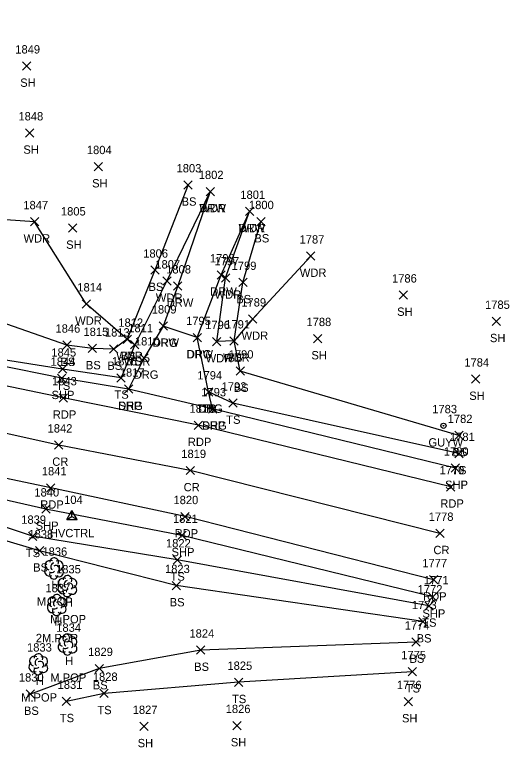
# Model space of a CAD drawing. Extents: x 1497084 to 1499861, y 734741 to 735567.
# Drawn here: x 1499741.8 to 1499860.6, y 735362.7 to 735538.6 of the extents above; entities that cross this region are included whole.
import ezdxf

# ---------------------------------------------------------------- set-up
doc = ezdxf.new("R2010")
doc.units = 0
for name, color, linetype in [('C_A', 7, 'Continuous'), ('C_I', 7, 'Continuous'), ('CPSM', 7, 'Continuous'), ('L_A', 7, 'Continuous'), ('L_C', 7, 'Continuous'), ('L_I', 7, 'Continuous'), ('L_TIC', 7, 'Continuous'), ('LAWA', 7, 'Continuous'), ('LELB', 7, 'Continuous'), ('LTD', 7, 'Continuous'), ('P_A', 7, 'Continuous'), ('P_I', 7, 'Continuous'), ('P_TIC', 7, 'Continuous'), ('PET', 7, 'Continuous'), ('PRC', 7, 'Continuous'), ('PSP', 7, 'Continuous'), ('R_A', 7, 'Continuous'), ('R_I', 7, 'Continuous'), ('R_TIC', 7, 'Continuous'), ('RDG', 7, 'Continuous'), ('RDW', 7, 'Continuous'), ('U_A', 7, 'Continuous'), ('U_I', 7, 'Continuous'), ('UPGW', 7, 'Continuous')]:
    doc.layers.add(name, color=color, linetype=linetype)

msp = doc.modelspace()

# ---------------------------------------------------------------- linework, layer by layer
at = {"layer": 'CPSM'}
for p, q in [((1499754.27, 735417.41), (1499755.52, 735419.57)), ((1499754.27, 735417.41), (1499755.52, 735418.13)), ((1499756.77, 735417.41), (1499755.52, 735419.57)), ((1499755.52, 735418.13), (1499755.52, 735419.57)), ((1499755.52, 735418.13), (1499755.52, 735418.13)), ((1499755.52, 735418.13), (1499756.77, 735417.41)), ((1499754.27, 735417.41), (1499756.77, 735417.41))]:
    msp.add_line(p, q, dxfattribs=at)
at = {"layer": 'L_TIC'}
for points in [[(1499743.61, 735525.3), (1499745.61, 735527.3)], [(1499745.61, 735525.3), (1499743.61, 735527.3)], [(1499744.36, 735509.23), (1499746.36, 735511.23)], [(1499746.36, 735509.23), (1499744.36, 735511.23)], [(1499760.88, 735501.14), (1499762.88, 735503.14)], [(1499762.88, 735501.14), (1499760.88, 735503.14)], [(1499782.41, 735496.75), (1499784.41, 735498.75)], [(1499784.41, 735496.75), (1499782.41, 735498.75)], [(1499787.74, 735495.15), (1499789.74, 735497.15)], [(1499789.74, 735495.15), (1499787.74, 735497.15)], [(1499797.16, 735490.39), (1499799.16, 735492.39)], [(1499799.16, 735490.39), (1499797.16, 735492.39)], [(1499745.53, 735487.9), (1499747.53, 735489.9)], [(1499747.53, 735487.9), (1499745.53, 735489.9)], [(1499799.89, 735487.93), (1499801.89, 735489.93)], [(1499801.89, 735487.93), (1499799.89, 735489.93)], [(1499754.65, 735486.4), (1499756.65, 735488.4)], [(1499756.65, 735486.4), (1499754.65, 735488.4)], [(1499811.88, 735479.66), (1499813.88, 735481.66)], [(1499813.88, 735479.66), (1499811.88, 735481.66)], [(1499774.46, 735476.28), (1499776.46, 735478.28)], [(1499776.46, 735476.28), (1499774.46, 735478.28)], [(1499791.43, 735474.42), (1499793.43, 735476.42)], [(1499793.43, 735474.42), (1499791.43, 735476.42)], [(1499777.31, 735473.67), (1499779.31, 735475.67)], [(1499779.31, 735473.67), (1499777.31, 735475.67)], [(1499795.56, 735473.32), (1499797.56, 735475.32)], [(1499797.56, 735473.32), (1499795.56, 735475.32)], [(1499834.12, 735470.3), (1499836.12, 735472.3)], [(1499836.12, 735470.3), (1499834.12, 735472.3)], [(1499757.94, 735468.15), (1499759.94, 735470.15)], [(1499759.94, 735468.15), (1499757.94, 735470.15)], [(1499797.89, 735464.54), (1499799.89, 735466.54)], [(1499799.89, 735464.54), (1499797.89, 735466.54)], [(1499856.41, 735463.98), (1499858.41, 735465.98)], [(1499858.41, 735463.98), (1499856.41, 735465.98)], [(1499753.32, 735458.26), (1499755.32, 735460.26)], [(1499755.32, 735458.26), (1499753.32, 735460.26)], [(1499767.79, 735459.68), (1499769.79, 735461.68)], [(1499769.79, 735459.68), (1499767.79, 735461.68)], [(1499767.79, 735459.68), (1499769.79, 735461.68)], [(1499769.79, 735459.68), (1499767.79, 735461.68)], [(1499769.6, 735458.37), (1499771.6, 735460.37)], [(1499771.6, 735458.37), (1499769.6, 735460.37)], [(1499769.6, 735458.37), (1499771.6, 735460.37)], [(1499771.6, 735458.37), (1499769.6, 735460.37)], [(1499789.27, 735459.12), (1499791.27, 735461.12)], [(1499791.27, 735459.12), (1499789.27, 735461.12)], [(1499793.46, 735459.27), (1499795.46, 735461.27)], [(1499795.46, 735459.27), (1499793.46, 735461.27)], [(1499793.46, 735459.27), (1499795.46, 735461.27)], [(1499795.46, 735459.27), (1499793.46, 735461.27)], [(1499813.53, 735459.84), (1499815.53, 735461.84)], [(1499815.53, 735459.84), (1499813.53, 735461.84)], [(1499759.42, 735457.46), (1499761.42, 735459.46)], [(1499761.42, 735457.46), (1499759.42, 735459.46)], [(1499764.57, 735457.33), (1499766.57, 735459.33)], [(1499766.57, 735457.33), (1499764.57, 735459.33)], [(1499752.27, 735452.51), (1499754.27, 735454.51)], [(1499754.27, 735452.51), (1499752.27, 735454.51)], [(1499794.94, 735452.04), (1499796.94, 735454.04)], [(1499796.94, 735452.04), (1499794.94, 735454.04)], [(1499766.32, 735450.4), (1499768.32, 735452.4)], [(1499768.32, 735450.4), (1499766.32, 735452.4)], [(1499851.45, 735450.11), (1499853.45, 735452.11)], [(1499853.45, 735450.11), (1499851.45, 735452.11)], [(1499787.32, 735447.02), (1499789.32, 735449.02)], [(1499789.32, 735447.02), (1499787.32, 735449.02)], [(1499793.16, 735444.36), (1499795.16, 735446.36)], [(1499795.16, 735444.36), (1499793.16, 735446.36)], [(1499847.45, 735436.58), (1499849.45, 735438.58)], [(1499849.45, 735436.58), (1499847.45, 735438.58)], [(1499847.43, 735432.23), (1499849.43, 735434.23)], [(1499849.43, 735432.23), (1499847.43, 735434.23)], [(1499745.05, 735412.36), (1499747.05, 735414.36)], [(1499747.05, 735412.36), (1499745.05, 735414.36)], [(1499746.75, 735408.88), (1499748.75, 735410.88)], [(1499748.75, 735408.88), (1499746.75, 735410.88)], [(1499779.79, 735406.69), (1499781.79, 735408.69)], [(1499781.79, 735406.69), (1499779.79, 735408.69)], [(1499779.55, 735400.53), (1499781.55, 735402.53)], [(1499781.55, 735400.53), (1499779.55, 735402.53)], [(1499840.23, 735395.64), (1499842.23, 735397.64)], [(1499842.23, 735395.64), (1499840.23, 735397.64)], [(1499838.85, 735391.86), (1499840.85, 735393.86)], [(1499840.85, 735391.86), (1499838.85, 735393.86)], [(1499837.14, 735386.97), (1499839.14, 735388.97)], [(1499839.14, 735386.97), (1499837.14, 735388.97)], [(1499785.43, 735385.03), (1499787.43, 735387.03)], [(1499787.43, 735385.03), (1499785.43, 735387.03)], [(1499761.09, 735380.61), (1499763.09, 735382.61)], [(1499763.09, 735380.61), (1499761.09, 735382.61)], [(1499836.28, 735379.85), (1499838.28, 735381.85)], [(1499838.28, 735379.85), (1499836.28, 735381.85)], [(1499794.55, 735377.29), (1499796.55, 735379.29)], [(1499796.55, 735377.29), (1499794.55, 735379.29)], [(1499744.54, 735374.47), (1499746.54, 735376.47)], [(1499746.54, 735374.47), (1499744.54, 735376.47)], [(1499762.22, 735374.64), (1499764.22, 735376.64)], [(1499764.22, 735374.64), (1499762.22, 735376.64)], [(1499753.2, 735372.72), (1499755.2, 735374.72)], [(1499755.2, 735372.72), (1499753.2, 735374.72)], [(1499835.28, 735372.67), (1499837.28, 735374.67)], [(1499837.28, 735372.67), (1499835.28, 735374.67)], [(1499794.18, 735366.91), (1499796.18, 735368.91)], [(1499796.18, 735366.91), (1499794.18, 735368.91)], [(1499771.8, 735366.7), (1499773.8, 735368.7)], [(1499773.8, 735366.7), (1499771.8, 735368.7)]]:
    msp.add_lwpolyline(points, dxfattribs=at)
at = {"layer": 'LAWA'}
for points in [[(1499788.74, 735496.15), (1499778.31, 735474.67), (1499770.6, 735459.37), (1499768.79, 735460.68), (1499758.94, 735469.15), (1499746.53, 735488.9), (1499729.21, 735490.09), (1499697.8, 735511.88), (1499637.79, 735524.78), (1499612.73, 735535.09), (1499594.49, 735538.63)], [(1499812.88, 735480.66), (1499798.89, 735465.54), (1499794.46, 735460.27), (1499790.27, 735460.12), (1499792.43, 735475.42), (1499798.16, 735491.39)]]:
    msp.add_lwpolyline(points, dxfattribs=at)
at = {"layer": 'LELB'}
for points in [[(1499783.41, 735497.75), (1499775.46, 735477.28), (1499768.79, 735460.68), (1499765.57, 735458.33), (1499760.42, 735458.46), (1499754.32, 735459.26), (1499738.22, 735464.85), (1499726.1, 735470.25), (1499689.55, 735474.19)], [(1499848.45, 735437.58), (1499795.94, 735453.04), (1499794.46, 735460.27), (1499796.56, 735474.32), (1499800.89, 735488.93)], [(1499770.6, 735459.37), (1499767.32, 735451.4), (1499753.27, 735453.51), (1499723.33, 735458.19), (1499688.04, 735465.79), (1499662, 735476.73), (1499649.94, 735471.98), (1499600.23, 735477.81), (1499596.97, 735472.37)], [(1499848.43, 735433.23), (1499794.16, 735445.36), (1499788.32, 735448.02)], [(1499839.85, 735392.86), (1499780.55, 735401.53), (1499747.75, 735409.88), (1499711.76, 735420.6), (1499681.47, 735424.66), (1499665.96, 735425.75), (1499648.83, 735427.4), (1499598.57, 735431.68), (1499589.95, 735436.64), (1499584.82, 735440.49), (1499583.81, 735444.46), (1499585.42, 735446.56), (1499592.69, 735446.66)], [(1499841.23, 735396.64), (1499780.79, 735407.69), (1499746.05, 735413.36), (1499713.07, 735424.39), (1499683.25, 735430.83), (1499665.3, 735431.61), (1499657.01, 735431.78), (1499644.89, 735434.35), (1499602.81, 735439.91), (1499596.15, 735442.52), (1499594.16, 735445.59)], [(1499838.14, 735387.97), (1499786.43, 735386.03), (1499762.09, 735381.61), (1499745.54, 735375.47)], [(1499837.28, 735380.85), (1499795.55, 735378.29), (1499763.22, 735375.64), (1499754.2, 735373.72)]]:
    msp.add_lwpolyline(points, dxfattribs=at)
at = {"layer": 'LTD'}
for p, q in [((1499751.18, 735405.69), (1499751.18, 735405.69)), ((1499751.18, 735405.69), (1499751.18, 735405.69)), ((1499754.39, 735401.46), (1499754.39, 735401.46)), ((1499754.39, 735401.46), (1499754.39, 735401.46)), ((1499751.84, 735396.93), (1499751.84, 735396.93)), ((1499751.84, 735396.93), (1499751.84, 735396.93)), ((1499754.43, 735387.42), (1499754.43, 735387.42)), ((1499754.43, 735387.42), (1499754.43, 735387.42)), ((1499747.42, 735382.68), (1499747.42, 735382.68)), ((1499747.42, 735382.68), (1499747.42, 735382.68))]:
    msp.add_line(p, q, dxfattribs=at)
for centre in [(1499751.23, 735407.13), (1499754.44, 735402.89), (1499751.88, 735398.36), (1499754.48, 735388.85), (1499747.47, 735384.12)]:
    msp.add_arc(centre, 1.05, 335.5272, 180.9563, dxfattribs=at)
for centre, major_axis, ratio, start_param, end_param in [((1499750.39, 735406.36), (1.21, -0.51), 0.895232, 1.570796, 4.712389), ((1499752.22, 735406.28), (-1.14, -0.48), 0.949671, 1.570796, 4.712389), ((1499750.1, 735404.98), (0.58, -1.04), 0.959034, 3.141593, 6.283185), ((1499750.97, 735406.15), (-0.208, -0.792), 0.645439, 3.141593, 6.283185), ((1499751.68, 735405.53), (-0.5, 0.667), 0.989748, 3.141593, 6.283185), ((1499752.18, 735404.86), (-1.09, 0.79), 0.841452, 1.570796, 4.712389), ((1499751.18, 735404.19), (0.26, 1.06), 0.942809, 1.570796, 4.712389), ((1499750.72, 735404.94), (-0.625, -0.083), 0.423636, 0, 3.141593), ((1499753.6, 735402.12), (1.21, -0.51), 0.895232, 1.570796, 4.712389), ((1499754.19, 735401.92), (-0.208, -0.792), 0.645439, 3.141593, 6.283185), ((1499754.89, 735401.29), (-0.5, 0.667), 0.989748, 3.141593, 6.283185), ((1499755.44, 735402.04), (-1.14, -0.48), 0.949671, 1.570796, 4.712389), ((1499753.31, 735400.75), (0.58, -1.04), 0.959034, 3.141593, 6.283185), ((1499753.94, 735400.71), (-0.625, -0.083), 0.423636, 0, 3.141593), ((1499755.39, 735400.63), (-1.09, 0.79), 0.841452, 1.570796, 4.712389), ((1499751.05, 735397.59), (1.21, -0.51), 0.895232, 1.570796, 4.712389), ((1499752.88, 735397.51), (-1.14, -0.48), 0.949671, 1.570796, 4.712389), ((1499754.4, 735399.96), (0.26, 1.06), 0.942809, 1.570796, 4.712389), ((1499750.75, 735396.22), (0.58, -1.04), 0.959034, 3.141593, 6.283185), ((1499751.63, 735397.39), (-0.208, -0.792), 0.645439, 3.141593, 6.283185), ((1499752.34, 735396.76), (-0.5, 0.667), 0.989748, 3.141593, 6.283185), ((1499752.84, 735396.09), (-1.09, 0.79), 0.841452, 1.570796, 4.712389), ((1499751.84, 735395.43), (0.26, 1.06), 0.942809, 1.570796, 4.712389), ((1499751.38, 735396.18), (-0.625, -0.083), 0.423636, 0, 3.141593), ((1499753.64, 735388.08), (1.21, -0.51), 0.895232, 1.570796, 4.712389), ((1499754.23, 735387.87), (-0.208, -0.792), 0.645439, 3.141593, 6.283185), ((1499754.93, 735387.25), (-0.5, 0.667), 0.989748, 3.141593, 6.283185), ((1499755.48, 735388), (-1.14, -0.48), 0.949671, 1.570796, 4.712389), ((1499753.35, 735386.71), (0.58, -1.04), 0.959034, 3.141593, 6.283185), ((1499753.98, 735386.67), (-0.625, -0.083), 0.423636, 0, 3.141593), ((1499755.44, 735386.58), (-1.09, 0.79), 0.841452, 1.570796, 4.712389), ((1499746.63, 735383.35), (1.21, -0.51), 0.895232, 1.570796, 4.712389), ((1499748.46, 735383.26), (-1.14, -0.48), 0.949671, 1.570796, 4.712389), ((1499754.44, 735385.92), (0.26, 1.06), 0.942809, 1.570796, 4.712389), ((1499746.34, 735381.97), (0.58, -1.04), 0.959034, 3.141593, 6.283185), ((1499747.21, 735383.14), (-0.208, -0.792), 0.645439, 3.141593, 6.283185), ((1499747.92, 735382.51), (-0.5, 0.667), 0.989748, 3.141593, 6.283185), ((1499747.42, 735381.18), (0.26, 1.06), 0.942809, 1.570796, 4.712389), ((1499746.96, 735381.93), (-0.625, -0.083), 0.423636, 0, 3.141593), ((1499748.42, 735381.85), (-1.09, 0.79), 0.841452, 1.570796, 4.712389)]:
    msp.add_ellipse(centre, major_axis=major_axis, ratio=ratio, start_param=start_param, end_param=end_param, dxfattribs=at)
at = {"layer": 'P_TIC'}
for points in [[(1499752.08, 735450.31), (1499754.08, 735452.31)], [(1499754.08, 735450.31), (1499752.08, 735452.31)], [(1499768.13, 735447.7), (1499770.13, 735449.7)], [(1499770.13, 735447.7), (1499768.13, 735449.7)], [(1499752.42, 735445.61), (1499754.42, 735447.61)], [(1499754.42, 735445.61), (1499752.42, 735447.61)], [(1499788.27, 735442.96), (1499790.27, 735444.96)], [(1499790.27, 735442.96), (1499788.27, 735444.96)], [(1499784.87, 735439.03), (1499786.87, 735441.03)], [(1499786.87, 735439.03), (1499784.87, 735441.03)], [(1499751.36, 735434.28), (1499753.36, 735436.28)], [(1499753.36, 735434.28), (1499751.36, 735436.28)], [(1499846.6, 735428.73), (1499848.6, 735430.73)], [(1499848.6, 735428.73), (1499846.6, 735430.73)], [(1499782.91, 735428.16), (1499784.91, 735430.16)], [(1499784.91, 735428.16), (1499782.91, 735430.16)], [(1499749.41, 735423.99), (1499751.41, 735425.99)], [(1499751.41, 735423.99), (1499749.41, 735425.99)], [(1499845.49, 735424.23), (1499847.49, 735426.23)], [(1499847.49, 735424.23), (1499845.49, 735426.23)], [(1499748.27, 735418.91), (1499750.27, 735420.91)], [(1499750.27, 735418.91), (1499748.27, 735420.91)], [(1499781.68, 735417.08), (1499783.68, 735419.08)], [(1499783.68, 735417.08), (1499781.68, 735419.08)], [(1499780.91, 735412.58), (1499782.91, 735414.58)], [(1499782.91, 735412.58), (1499780.91, 735414.58)], [(1499842.89, 735413.07), (1499844.89, 735415.07)], [(1499844.89, 735413.07), (1499842.89, 735415.07)], [(1499841.35, 735401.93), (1499843.35, 735403.93)], [(1499843.35, 735401.93), (1499841.35, 735403.93)], [(1499841.15, 735397.82), (1499843.15, 735399.82)], [(1499843.15, 735397.82), (1499841.15, 735399.82)]]:
    msp.add_lwpolyline(points, dxfattribs=at)
at = {"layer": 'PET'}
for points in [[(1499842.35, 735402.93), (1499782.68, 735418.08), (1499750.41, 735424.99), (1499714.98, 735432.41), (1499683.04, 735438.06), (1499645.69, 735442.94), (1499594.85, 735447.92), (1499595.43, 735458.81), (1499596.08, 735469.99)], [(1499846.49, 735425.23), (1499785.87, 735440.03), (1499753.42, 735446.61), (1499720.62, 735453.44), (1499687.53, 735458.83), (1499650.76, 735464.5), (1499635.87, 735466.46), (1499596.08, 735469.99)]]:
    msp.add_lwpolyline(points, dxfattribs=at)
at = {"layer": 'PRC'}
msp.add_lwpolyline([(1499843.89, 735414.07), (1499783.91, 735429.16), (1499752.36, 735435.28), (1499717.65, 735442.89), (1499685.25, 735448), (1499648.69, 735453.84), (1499595.43, 735458.81)], dxfattribs=at)
at = {"layer": 'PSP'}
for points in [[(1499847.6, 735429.73), (1499789.27, 735443.96), (1499769.13, 735448.7), (1499753.08, 735451.31), (1499721.43, 735457.75), (1499687.71, 735461.33), (1499651.84, 735466.26), (1499635.87, 735466.46)], [(1499842.15, 735398.82), (1499781.91, 735413.58), (1499749.27, 735419.91), (1499713.95, 735427.86), (1499683.22, 735436.06), (1499645.69, 735442.94)]]:
    msp.add_lwpolyline(points, dxfattribs=at)
at = {"layer": 'R_TIC'}
for points in [[(1499787.74, 735495.15), (1499789.74, 735497.15)], [(1499789.74, 735495.15), (1499787.74, 735497.15)], [(1499797.16, 735490.39), (1499799.16, 735492.39)], [(1499799.16, 735490.39), (1499797.16, 735492.39)], [(1499790.35, 735475.13), (1499792.35, 735477.13)], [(1499792.35, 735475.13), (1499790.35, 735477.13)], [(1499779.92, 735472.47), (1499781.92, 735474.47)], [(1499781.92, 735472.47), (1499779.92, 735474.47)], [(1499776.46, 735462.86), (1499778.46, 735464.86)], [(1499778.46, 735462.86), (1499776.46, 735464.86)], [(1499776.46, 735462.86), (1499778.46, 735464.86)], [(1499778.46, 735462.86), (1499776.46, 735464.86)], [(1499784.62, 735460.09), (1499786.62, 735462.09)], [(1499786.62, 735460.09), (1499784.62, 735462.09)], [(1499784.62, 735460.09), (1499786.62, 735462.09)], [(1499786.62, 735460.09), (1499784.62, 735462.09)], [(1499771.85, 735455.19), (1499773.85, 735457.19)], [(1499773.85, 735455.19), (1499771.85, 735457.19)], [(1499768.13, 735447.7), (1499770.13, 735449.7)], [(1499770.13, 735447.7), (1499768.13, 735449.7)], [(1499787.32, 735447.02), (1499789.32, 735449.02)], [(1499789.32, 735447.02), (1499787.32, 735449.02)], [(1499788.27, 735442.96), (1499790.27, 735444.96)], [(1499790.27, 735442.96), (1499788.27, 735444.96)]]:
    msp.add_lwpolyline(points, dxfattribs=at)
at = {"layer": 'RDG'}
msp.add_lwpolyline([(1499789.27, 735443.96), (1499788.32, 735448.02), (1499785.62, 735461.09), (1499777.46, 735463.86), (1499772.85, 735456.19), (1499769.13, 735448.7)], dxfattribs=at)
at = {"layer": 'RDW'}
for points in [[(1499788.74, 735496.15), (1499780.92, 735473.47), (1499777.46, 735463.86)], [(1499785.62, 735461.09), (1499791.35, 735476.13), (1499798.16, 735491.39)]]:
    msp.add_lwpolyline(points, dxfattribs=at)
at = {"layer": 'UPGW'}
for radius in [0.625, 0.0833]:
    msp.add_circle((1499844.74, 735439.91), radius, dxfattribs=at)

# ---------------------------------------------------------------- texts
at = {"layer": 'C_A'}
msp.add_text('HVCTRL', height=2, dxfattribs=at).set_placement((1499750.21, 735413.13))
at = {"layer": 'C_I'}
msp.add_text('104', height=2, dxfattribs=at).set_placement((1499753.64, 735421.13))
at = {"layer": 'L_A'}
for s, p in [('SH', (1499743.1, 735521.3)), ('SH', (1499743.85, 735505.23)), ('SH', (1499760.36, 735497.14)), ('BS', (1499781.85, 735492.75)), ('WDR', (1499786.1, 735491.15)), ('WDR', (1499795.52, 735486.39)), ('WDR', (1499743.89, 735483.9)), ('BS', (1499799.33, 735483.93)), ('SH', (1499754.13, 735482.4)), ('WDR', (1499810.24, 735475.66)), ('BS', (1499773.9, 735472.28)), ('WDR', (1499775.67, 735469.67)), ('WDR', (1499789.79, 735470.42)), ('BS', (1499795, 735469.32)), ('SH', (1499833.61, 735466.3)), ('WDR', (1499756.3, 735464.15)), ('WDR', (1499796.25, 735460.54)), ('SH', (1499855.9, 735459.98)), ('WDR', (1499766.15, 735455.68)), ('BS', (1499767.23, 735455.68)), ('WDR', (1499787.63, 735455.12)), ('WDR', (1499791.82, 735455.27)), ('BS', (1499792.9, 735455.27)), ('SH', (1499813.02, 735455.84)), ('BS', (1499752.76, 735454.26)), ('BS', (1499758.86, 735453.46)), ('BS', (1499764.01, 735453.33)), ('WDR', (1499767.96, 735454.37)), ('TS', (1499769.01, 735454.37)), ('TS', (1499751.68, 735448.51)), ('BS', (1499794.38, 735448.04)), ('TS', (1499765.73, 735446.4)), ('SH', (1499850.93, 735446.11)), ('TS', (1499786.73, 735443.02)), ('TS', (1499792.57, 735440.36)), ('BS', (1499846.89, 735432.58)), ('TS', (1499846.84, 735428.23)), ('TS', (1499744.46, 735408.36)), ('BS', (1499746.2, 735404.88)), ('TS', (1499779.2, 735402.69)), ('H', (1499750.61, 735400.69)), ('H', (1499753.83, 735396.46)), ('BS', (1499778.99, 735396.53)), ('H', (1499751.27, 735391.93)), ('TS', (1499839.64, 735391.64)), ('BS', (1499838.29, 735387.86)), ('BS', (1499836.58, 735382.97)), ('H', (1499753.87, 735382.42)), ('BS', (1499784.87, 735381.03)), ('H', (1499746.85, 735377.68)), ('BS', (1499760.53, 735376.61)), ('TS', (1499835.69, 735375.85)), ('TS', (1499793.96, 735373.29)), ('BS', (1499743.99, 735370.47)), ('TS', (1499761.63, 735370.64)), ('TS', (1499752.61, 735368.72)), ('SH', (1499834.77, 735368.67)), ('SH', (1499771.29, 735362.7)), ('SH', (1499793.67, 735362.91))]:
    msp.add_text(s, height=2, dxfattribs=at).set_placement(p)
at = {"layer": 'L_C'}
for s, p in [('M.POP', (1499747.08, 735396.69)), ('M.POP', (1499750.29, 735392.46)), ('2M.POP', (1499746.84, 735387.93)), ('M.POP', (1499750.33, 735378.42)), ('M.POP', (1499743.32, 735373.68))]:
    msp.add_text(s, height=2, dxfattribs=at).set_placement(p)
at = {"layer": 'L_I'}
for s, p in [('1849', (1499741.91, 735529.3)), ('1848', (1499742.67, 735513.23)), ('1804', (1499759.1, 735505.14)), ('1803', (1499780.64, 735500.75)), ('1802', (1499785.97, 735499.15)), ('1801', (1499795.96, 735494.39)), ('1847', (1499743.84, 735491.9)), ('1800', (1499798.03, 735491.93)), ('1805', (1499752.87, 735490.4)), ('1787', (1499810.18, 735483.66)), ('1806', (1499772.64, 735480.28)), ('1807', (1499775.54, 735477.67)), ('1797', (1499789.74, 735478.42)), ('1799', (1499793.86, 735477.32)), ('1786', (1499832.38, 735474.3)), ('1814', (1499756.81, 735472.15)), ('1789', (1499796.19, 735468.54)), ('1785', (1499854.72, 735467.98)), ('1812', (1499766.66, 735463.68)), ('1812', (1499766.66, 735463.68)), ('1788', (1499811.84, 735463.84)), ('1846', (1499751.57, 735462.26)), ('1811', (1499769.04, 735462.37)), ('1811', (1499769.04, 735462.37)), ('1796', (1499787.52, 735463.12)), ('1791', (1499792.33, 735463.27)), ('1791', (1499792.33, 735463.27)), ('1815', (1499758.29, 735461.46)), ('1813', (1499763.44, 735461.33)), ('1845', (1499750.57, 735456.51)), ('1790', (1499793.16, 735456.04)), ('1816', (1499765.14, 735454.4)), ('1784', (1499849.75, 735454.11)), ('1794', (1499785.63, 735451.02)), ('1792', (1499791.47, 735448.36)), ('1782', (1499845.75, 735440.58)), ('1781', (1499846.3, 735436.23)), ('1839', (1499743.34, 735416.36)), ('1838', (1499745.06, 735412.88)), ('1822', (1499778.1, 735410.69)), ('1836', (1499748.43, 735408.69)), ('1835', (1499751.7, 735404.46)), ('1823', (1499777.86, 735404.53)), ('1837', (1499749.15, 735399.93)), ('1772', (1499838.54, 735399.64)), ('1773', (1499837.16, 735395.86)), ('1834', (1499751.74, 735390.42)), ('1774', (1499835.44, 735390.97)), ('1824', (1499783.73, 735389.03)), ('1833', (1499744.73, 735385.68)), ('1829', (1499759.39, 735384.61)), ('1775', (1499834.59, 735383.85)), ('1825', (1499792.86, 735381.29)), ('1830', (1499742.77, 735378.47)), ('1828', (1499760.53, 735378.64)), ('1831', (1499752.08, 735376.72)), ('1776', (1499833.53, 735376.67)), ('1827', (1499770.11, 735370.7)), ('1826', (1499792.44, 735370.91))]:
    msp.add_text(s, height=2, dxfattribs=at).set_placement(p)
at = {"layer": 'P_A'}
for s, p in [('SHP', (1499750.62, 735446.31)), ('SHP', (1499766.67, 735443.7)), ('RDP', (1499750.91, 735441.61)), ('SHP', (1499786.8, 735438.96)), ('RDP', (1499783.35, 735435.03)), ('CR', (1499750.79, 735430.28)), ('CR', (1499782.34, 735424.16)), ('SHP', (1499845.13, 735424.73)), ('RDP', (1499747.9, 735419.99)), ('RDP', (1499843.98, 735420.23)), ('SHP', (1499746.8, 735414.91)), ('RDP', (1499780.17, 735413.08)), ('CR', (1499842.32, 735409.07)), ('SHP', (1499779.44, 735408.58)), ('RDP', (1499839.84, 735397.93)), ('SHP', (1499839.68, 735393.82))]:
    msp.add_text(s, height=2, dxfattribs=at).set_placement(p)
at = {"layer": 'P_I'}
for s, p in [('1844', (1499750.39, 735454.31)), ('1817', (1499767.01, 735451.7)), ('1843', (1499750.73, 735449.61)), ('1793', (1499786.57, 735446.96)), ('1818', (1499783.74, 735443.03)), ('1842', (1499749.67, 735438.28)), ('1819', (1499781.78, 735432.16)), ('1780', (1499844.82, 735432.73)), ('1841', (1499748.28, 735427.99)), ('1779', (1499843.79, 735428.23)), ('1840', (1499746.49, 735422.91)), ('1820', (1499779.9, 735421.08)), ('1821', (1499779.78, 735416.58)), ('1778', (1499841.19, 735417.07)), ('1777', (1499839.66, 735405.93)), ('1771', (1499840.02, 735401.82))]:
    msp.add_text(s, height=2, dxfattribs=at).set_placement(p)
at = {"layer": 'R_A'}
for s, p in [('DRW', (1499786.11, 735491.15)), ('DRW', (1499795.53, 735486.39)), ('DRW', (1499788.72, 735471.13)), ('DRW', (1499778.29, 735468.47)), ('DRW', (1499774.83, 735458.86)), ('DRG', (1499774.94, 735458.86)), ('DRW', (1499782.99, 735456.09)), ('DRG', (1499783.11, 735456.09)), ('DRG', (1499770.34, 735451.19)), ('DRG', (1499766.62, 735443.7)), ('DRG', (1499785.81, 735443.02)), ('DRG', (1499786.76, 735438.96))]:
    msp.add_text(s, height=2, dxfattribs=at).set_placement(p)
at = {"layer": 'R_I'}
for s, p in [('1802', (1499785.97, 735499.15)), ('1801', (1499795.96, 735494.39)), ('1798', (1499788.66, 735479.13)), ('1808', (1499778.15, 735476.47)), ('1809', (1499774.68, 735466.86)), ('1809', (1499774.68, 735466.86)), ('1795', (1499782.93, 735464.09)), ('1795', (1499782.93, 735464.09)), ('1810', (1499770.64, 735459.19)), ('1817', (1499767.01, 735451.7)), ('1794', (1499785.63, 735451.02)), ('1793', (1499786.57, 735446.96))]:
    msp.add_text(s, height=2, dxfattribs=at).set_placement(p)
at = {"layer": 'U_A'}
msp.add_text('GUYW', height=2, dxfattribs=at).set_placement((1499841.13, 735434.91))
at = {"layer": 'U_I'}
msp.add_text('1783', height=2, dxfattribs=at).set_placement((1499842.04, 735442.91))

doc.saveas('drawing.dxf')
